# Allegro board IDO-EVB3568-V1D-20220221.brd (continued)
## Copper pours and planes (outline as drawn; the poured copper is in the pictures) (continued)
VDD_USB_5V on VCC: 104.01,89.03 101.47,86.49 101.47,84.96 95.76,79.25 91.44,79.25 90.3,80.39 82.93,80.39 82.55,80.01 76.83,80.01 76.33,79.5 71.63,79.5 70.99,78.87 57.02,78.87 55.24,80.64 52.07,80.64 50.93,79.5 49.28,79.5 48.9,79.88 48.9,84.07 49.15,84.33 68.71,84.33 71.25,81.79 75.44,81.79 77.22,83.57 84.84,83.57 85.98,82.42 90.3,82.42 90.42,82.55 90.42,97.54 93.09,100.2 139.34,100.2 141.1,98.45 141.1,84.96 137.03,80.9 137.03,72.01 136.02,70.99 136.02,69.34 134.75,68.07 134.75,62.48 133.35,61.09 133.35,58.55 136.78,55.12 143.13,55.12 144.27,53.98 144.27,11.18 143.64,10.54 140.84,10.54 140.59,10.79 140.59,12.83 142.88,15.11 142.88,50.8 142.49,51.18 133.48,51.18 132.97,50.67 132.97,48.9 134.62,47.24 134.62,44.2 134.24,43.81 132.84,43.81 130.81,45.85 130.81,70.74 134.49,74.42 134.49,87.88 133.35,89.03
GM_VDDIO on TOP: 31.75,29.08 31.75,27.91 30.63,26.8 30.63,20.09 30.15,19.61 28.83,19.61 28.65,19.79 28.65,20.47 28.78,20.6 29.16,20.6 29.46,20.29 29.87,20.29 30.02,20.45 30.02,20.78 29.39,21.41 29.39,22.07 29.41,22.1 29.41,22.56 29.26,22.71 28.7,22.71 28.45,22.45 28.45,22.1 28.3,21.95 27.48,21.95 27.25,22.17 27.25,22.89 26.82,23.32 26.82,23.77 26.52,24.08 25.6,24.08 25.45,24.23 25.45,24.38 25.6,24.54 27.2,24.54 27.58,24.16 27.58,23.47 27.74,23.32 29.26,23.32 29.41,23.47 29.41,25.15 29.26,25.3 28.8,25.3 28.5,25.6 28.5,26.06 28.35,26.21 27.74,26.21 27.13,25.6 25.3,25.6 25.15,25.76 25.15,26.54 25.27,26.67 26.67,26.67 27.69,27.69 29.84,27.69 30.61,28.45 30.61,28.96 31.11,29.46 31.37,29.46
GM_VDDIO on BOTTOM: 35.36,28.07 35.36,29.13 35.23,29.26 32.41,29.26 32.21,29.46 31.11,29.46 30.99,29.34 30.99,29.08 32,28.07
LVDS_VIO on TOP: 46.86,12.06 49.66,12.06 49.91,12.32 49.91,13.08 50.16,13.34 53.59,13.34 53.85,13.08 53.85,10.67 53.59,10.41 42.55,10.41 42.42,10.54 42.42,12.32 43.31,13.21 46.35,13.21 46.48,13.08 46.48,12.45
LVDS_VIO_ on TOP: 38.1,13.46 39.24,13.46 40.77,14.99 42.29,14.99 42.42,14.86 42.42,13.84 42.29,13.72 41.53,13.72 40.26,12.45 40.26,6.22 40.01,5.97 38.61,5.97 38.23,6.35 38.23,8.13 37.97,8.38 36.7,8.38 36.45,8.64 36.45,10.29 37.85,11.68 37.85,13.21
PHY0_REG_OUT on BOTTOM: 105.16,68.88 105.16,68.2 105.13,68.17 104.9,68.17 104.8,68.28 103.58,68.28 103.5,68.2 102.74,68.2 101.47,66.93 100.71,66.93 100.58,67.06 100.58,68.83 100.71,68.96 102.23,68.96 102.36,68.83 102.87,68.83 102.92,68.88
PHY1_REG_OUT on BOTTOM: 119.15,67.08 119.18,67.06 119.18,66.6 119.02,66.45 118.11,66.45 117.5,65.84 117.5,64.77 117.35,64.62 116.74,64.62 116.59,64.77 116.59,66.9 116.74,67.06 117.65,67.06 117.68,67.08
SPK_5V on BOTTOM: 99.82,21.08 99.82,12.06 100.33,11.56 100.33,10.92 100.58,10.67 101.22,10.67 101.35,10.79 101.35,12.06 100.84,12.57 100.84,20.57 101.6,21.34 103.63,21.34 103.76,21.46 103.76,22.23 103.63,22.35 101.09,22.35
N17053342 on TOP: 106.38,58.98 106.38,58.52 106.27,58.42 105.16,58.42 104.65,58.93 104.01,58.93 103.89,59.05 103.89,60.71 103.25,61.34 103.25,64.64 103.38,64.77 105.18,64.77 105.31,64.64 105.31,60.05
N17053434 on TOP: 106.22,64.69 106.22,61.42 106.38,61.26 106.98,61.26 107.44,60.81 107.44,59.44 107.59,59.28 108.05,59.28 108.2,59.44 108.2,64.64 108.08,64.77 106.3,64.77
N67228394 on TOP: 60.83,84.33 62.61,84.33 62.87,84.07 62.87,83.06 62.99,82.93 63.88,82.93 63.88,82.55 62.99,82.55 62.48,82.04 62.48,81.53 62.61,81.41 64.01,81.41 64.14,81.28 64.14,80.77 64.01,80.64 62.61,80.64 62.48,80.77 60.71,80.77 60.71,84.2
N67269040 on BOTTOM: 43.18,32.13 48.26,32.13 48.51,31.88 48.51,29.97 46.99,28.45 46.99,27.43 46.74,27.18 45.03,27.18 44.7,27.51 44.7,28.45 42.93,30.23 42.93,31.88
N68391237 on BOTTOM: 34.16,47.37 34.29,47.24 34.29,45.34 34.16,45.21 33.4,45.21 33.27,45.34 33.27,45.72 32.64,46.35 32.13,46.35 31.88,46.61 31.88,47.24 32,47.37
N68444772 on TOP: 14.02,83.97 20.02,83.97 20.32,83.67 20.32,81.64 18.29,81.64 17.63,82.3 16.1,82.3 15.72,82.68 14.15,82.68 14.02,82.8
N68444772 on BOTTOM: 5.46,80.9 9.53,76.83 9.53,74.3 9.78,74.04 19.3,74.04 21.72,76.45 21.72,83.03 18.9,85.85 5.59,85.85 5.46,85.72
N68558638 on TOP: 12.62,31.42 14.27,31.42 14.43,31.27 14.43,29.9 13.56,29.03 13.56,26.92 13.23,26.59 13.23,25.53 13.21,25.5 12.12,25.5 12.12,26.14 12.42,26.44 12.42,31.22
N68610828 on TOP: 125.09,60.07 127.89,60.07 128.02,59.94 128.02,59.18 127.89,59.05 126.87,59.05 126.11,58.29 125.09,58.29 124.97,58.42 124.97,59.94
N68721931 on TOP: 105.03,41.27 105.03,39.5 105.16,39.37 107.44,39.37 107.57,39.5 107.57,39.88 107.44,40.01 106.3,40.01 106.05,40.26 106.05,41.27 105.92,41.4 105.16,41.4
N68764417 on TOP: 26.24,49.66 26.54,49.66 26.54,49.02 26.59,48.97 26.75,48.97 26.86,48.86 27.37,48.86 27.38,48.84 28.3,48.84 28.52,49.07 29.01,49.07 29.08,49 29.08,46.94 28.8,46.66 25.53,46.66 25.48,46.71 25.48,48.51 25.86,48.9 26.06,48.9 26.21,49.05 26.21,49.63
N68886075 on TOP (solid shape): 135.19,84.56 135.01,84.38 134.09,84.38 133.82,84.8 134.42,85.32

Small or netless copper shapes (teardrops, artwork), in the pictures only: 261 on TOP, 14 on BOTTOM, 2 on GND

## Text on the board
Ref Des/Silkscreen Bottom: 5V | GND | FDP6 | FDM6 | FDP5 | FDM5 | FDP4 | FDM4 | PWON | MISO | MOSI | ADC5 | ADC4 | ADC2 | PWM7 | CS0 | CLK | OR | 0T | G | 3R | 3T | 4R | 4T | 5R | 5T | 7R | 7T | 1H | 1HL | 2H | 2L | L_D7N | L_D7P | 12V | L_CKN | L_CKP | L_D6N | L_D6P | L_D5N | L_D5P | L_D4N | L_D4P | L_D3N | L_D3P | L_D2N | L_D2P | L_D1N | L_D1P | L_D0N | L_D0P | L_VIO | NC | 3.3V | L_PWM | L_ON | STXP | 3V3 | E_HPD | STXN | E_D3N | E_D3P | SRXN | E_CKN | E_CKP | SRXP | E_D2N | E_D2P | E_D1N | E_D1P | E_D0N | E_D0P | E_VIO | E_PWM | E_ON | MIC1P | MIPI-DSI0 | IDO-EVB3568-V1D | MIPI-DSI1
Ref Des/Silkscreen Top: J2 | J32 | J36 | J33 | J35 | J34 | J39 | LED | J1 | J28 | J26 | J18 | J27 | OTG | J6 | J5 | J25 | J8 | J19 | J21 | J7 | J9 | J20 | J15 | J30 | J4 | J17 | J31 | J3 | RECOVERY | J40 | J16 | J12 | J11 | J13 | J14 | J10
User.15: FIGURE | SIZE | 8.0 | 11.811 | 27.559 | 27.6 | 28.0 | 29.134 | 31.496 | 32.0 | 35.0 | 36.0 | 39.37 | 40.0 | 53.15 | 65.0 | 66.929 | 91.0 | 93.0 | 118.11 | 165.35 | 43.0 | 45.0 | 55.0 | 63.0 | 90.551 | 128.0 | 66.929x35.429 | 78.74x23.622 | 78.74x31.5 | 106.299x35.429 | DRILL CHART: TOP to BOTTOM | ALL UNITS ARE IN MILS | PLATED | NON-PLATED | QTY | 1303 | 807 | 50 | 16 | 18 | 7 | 12 | 3 | 30 | 20 | 1 | 4 | 2 | 8 | 14
